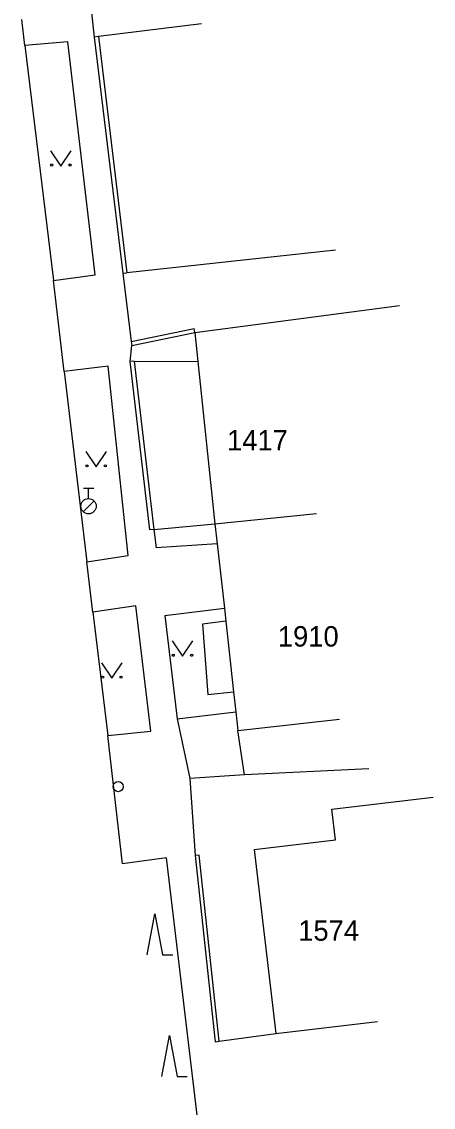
# Model space of a CAD drawing. Extents: x -539515 to -538098, y -1182060 to -1180157.
# Drawn here: x -539478.4 to -539458.3, y -1180484.4 to -1180431.3 of the extents above; entities that cross this region are included whole.
import ezdxf

# ---------------------------------------------------------------- set-up
doc = ezdxf.new("R2010")
doc.units = 0
for name, color, linetype in [('Vrstva 10', 7, 'Continuous'), ('Vrstva 11', 7, 'Continuous'), ('Vrstva 28', 7, 'Continuous'), ('Vrstva 36', 7, 'Continuous'), ('Vrstva 47', 7, 'Continuous'), ('Vrstva 5', 7, 'Continuous'), ('Vrstva 7', 7, 'Continuous'), ('Vrstva 8', 7, 'Continuous')]:
    doc.layers.add(name, color=color, linetype=linetype)

msp = doc.modelspace()

# ---------------------------------------------------------------- linework, layer by layer
at = {"layer": 'Vrstva 10'}
for p, q in [((-539478.28, -1180432.453), (-539478.43, -1180431.188)), ((-539478.28, -1180432.453), (-539476.88, -1180443.953)), ((-539476.36, -1180448.406), (-539476.88, -1180443.953)), ((-539476.36, -1180448.406), (-539475.24, -1180457.719)), ((-539474.95, -1180460.188), (-539475.24, -1180457.719)), ((-539474.95, -1180460.188), (-539474.22, -1180466.219)), ((-539473.5, -1180472.492), (-539474.22, -1180466.219))]:
    msp.add_line(p, q, dxfattribs=at)
at = {"layer": 'Vrstva 11'}
for p, q in [((-539469.641, -1180431.406), (-539474.682, -1180432.023)), ((-539476.17, -1180432.289), (-539478.28, -1180432.453)), ((-539474.83, -1180443.688), (-539476.17, -1180432.289)), ((-539476.88, -1180443.953), (-539474.83, -1180443.688)), ((-539473.13, -1180447.914), (-539473.04, -1180447.133)), ((-539474.2, -1180448.148), (-539476.36, -1180448.406)), ((-539473.22, -1180457.406), (-539474.2, -1180448.148)), ((-539472.93, -1180447.898), (-539469.812, -1180447.923)), ((-539468.868, -1180456.849), (-539471.85, -1180457.04)), ((-539475.24, -1180457.719), (-539473.22, -1180457.406)), ((-539472.85, -1180459.867), (-539474.95, -1180460.188)), ((-539472.11, -1180466), (-539472.85, -1180459.867)), ((-539471.43, -1180460.352), (-539468.511, -1180459.99)), ((-539470.82, -1180465.406), (-539467.959, -1180465.056)), ((-539474.22, -1180466.219), (-539472.11, -1180466)), ((-539467.53, -1180468.148), (-539467.86, -1180465.969)), ((-539471.35, -1180472.203), (-539473.5, -1180472.492)), ((-539468.75, -1180494.039), (-539471.35, -1180472.203))]:
    msp.add_line(p, q, dxfattribs=at)
at = {"layer": 'Vrstva 28'}
for p, q in [((-539475.41, -1180454.125), (-539474.91, -1180454.125)), ((-539475.16, -1180454.625), (-539475.16, -1180454.125)), ((-539475.418, -1180455.272), (-539474.888, -1180454.742))]:
    msp.add_line(p, q, dxfattribs=at)
for centre, radius in [((-539475.16, -1180455), 0.375), ((-539473.71, -1180468.719), 0.25)]:
    msp.add_circle(centre, radius, dxfattribs=at)
at = {"layer": 'Vrstva 36'}
for points in [[(-539477.016, -1180437.609), (-539476.516, -1180438.359), (-539476.016, -1180437.609)], [(-539475.289, -1180452.32), (-539474.789, -1180453.07), (-539474.289, -1180452.32)], [(-539471.066, -1180461.594), (-539470.566, -1180462.344), (-539470.066, -1180461.594)], [(-539474.521, -1180462.664), (-539474.021, -1180463.414), (-539473.521, -1180462.664)], [(-539472.292, -1180476.95), (-539471.917, -1180474.95), (-539471.542, -1180476.95), (-539471.042, -1180476.95)], [(-539471.584, -1180482.895), (-539471.209, -1180480.895), (-539470.834, -1180482.895), (-539470.334, -1180482.895)]]:
    msp.add_lwpolyline(points, dxfattribs=at)
for centre in [(-539476.966, -1180438.309), (-539476.067, -1180438.309), (-539475.239, -1180453.02), (-539474.34, -1180453.02), (-539471.016, -1180462.294), (-539470.117, -1180462.294), (-539474.471, -1180463.364), (-539473.572, -1180463.364)]:
    msp.add_circle(centre, 0.05, dxfattribs=at)
at = {"layer": 'Vrstva 5'}
for p, q in [((-539469.96, -1180446.508), (-539459.95, -1180445.188)), ((-539469.96, -1180446.508), (-539469.812, -1180447.923)), ((-539469.812, -1180447.923), (-539468.98, -1180455.867)), ((-539468.98, -1180455.867), (-539464.006, -1180455.359)), ((-539468.98, -1180455.867), (-539468.868, -1180456.849)), ((-539468.868, -1180456.849), (-539468.511, -1180459.99)), ((-539468.511, -1180459.99), (-539468.44, -1180460.617)), ((-539468.44, -1180460.617), (-539469.58, -1180460.773)), ((-539469.58, -1180460.773), (-539469.32, -1180464.211)), ((-539468.44, -1180460.617), (-539468.065, -1180464.078)), ((-539469.32, -1180464.211), (-539468.065, -1180464.078)), ((-539468.065, -1180464.078), (-539467.959, -1180465.056)), ((-539467.959, -1180465.056), (-539467.86, -1180465.969)), ((-539467.86, -1180465.969), (-539462.891, -1180465.422)), ((-539463.265, -1180469.828), (-539458.299, -1180469.242)), ((-539463.087, -1180471.32), (-539463.265, -1180469.828)), ((-539467.06, -1180471.789), (-539463.087, -1180471.32)), ((-539467.06, -1180471.789), (-539466, -1180480.797)), ((-539466, -1180480.797), (-539461.034, -1180480.211))]:
    msp.add_line(p, q, dxfattribs=at)
at = {"layer": 'Vrstva 7'}
for p, q in [((-539475.01, -1180430.867), (-539474.88, -1180432.047)), ((-539474.682, -1180432.023), (-539474.88, -1180432.047)), ((-539474.88, -1180432.047), (-539473.48, -1180443.602)), ((-539474.682, -1180432.023), (-539473.282, -1180443.578)), ((-539463.09, -1180442.477), (-539473.282, -1180443.578)), ((-539473.48, -1180443.602), (-539473.282, -1180443.578)), ((-539473.48, -1180443.602), (-539473.08, -1180446.938)), ((-539473.08, -1180446.938), (-539470, -1180446.313)), ((-539473.04, -1180447.133), (-539469.96, -1180446.508)), ((-539469.96, -1180446.508), (-539470, -1180446.313)), ((-539473.08, -1180446.938), (-539473.04, -1180447.133)), ((-539472.93, -1180447.898), (-539473.13, -1180447.914)), ((-539472.17, -1180456.156), (-539473.13, -1180447.914)), ((-539472.93, -1180447.898), (-539471.97, -1180456.141)), ((-539471.97, -1180456.141), (-539472.17, -1180456.156)), ((-539471.97, -1180456.141), (-539468.98, -1180455.867)), ((-539471.97, -1180456.141), (-539471.85, -1180457.04)), ((-539471.43, -1180460.352), (-539470.82, -1180465.406)), ((-539470.82, -1180465.406), (-539470.2, -1180468.32)), ((-539461.451, -1180467.844), (-539467.53, -1180468.148)), ((-539467.53, -1180468.148), (-539470.2, -1180468.32)), ((-539469.751, -1180472.07), (-539469.95, -1180472.094)), ((-539469.95, -1180472.094), (-539468.97, -1180481.203)), ((-539468.771, -1180481.18), (-539469.751, -1180472.07)), ((-539468.97, -1180481.203), (-539468.771, -1180481.18)), ((-539468.771, -1180481.18), (-539466, -1180480.797))]:
    msp.add_line(p, q, dxfattribs=at)
at = {"layer": 'Vrstva 8'}
msp.add_line((-539470.2, -1180468.32), (-539469.95, -1180472.094), dxfattribs=at)

# ---------------------------------------------------------------- texts
at = {"layer": 'Vrstva 47'}
for s, p in [('1417', (-539468.387, -1180452.273)), ('1910', (-539465.901, -1180461.867)), ('1574', (-539464.905, -1180476.258))]:
    msp.add_text(s, height=1, dxfattribs=at).set_placement(p)

doc.saveas('drawing.dxf')
